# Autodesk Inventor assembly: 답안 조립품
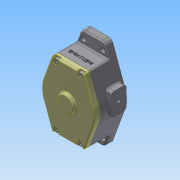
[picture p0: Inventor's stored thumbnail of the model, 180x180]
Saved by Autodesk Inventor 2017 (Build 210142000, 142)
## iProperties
Part Number: 답안 조립품
Material: 일반
Document SubType Name: Assembly
Designer: MRC
Author: MRC
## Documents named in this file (14)
- C:\Users\MRC\Desktop\731106V1008\답안 조립품.iam
- C:\Users\MRC\Desktop\731106V1008\본체.ipt
- C:\Users\MRC\Desktop\731106V1008\축.ipt
- C:\Users\MRC\Desktop\731106V1008\오일 실 14 25 4.ipt
- C:\Users\MRC\Desktop\731106V1008\오일레스 부시.ipt
- C:\Users\MRC\Desktop\731106V1008\내접기어.ipt
- C:\Users\MRC\Desktop\731106V1008\O링 G90.ipt
- C:\Users\MRC\Desktop\731106V1008\DU 부시.ipt
- C:\Users\MRC\Desktop\731106V1008\크레센트.ipt
- C:\Users\MRC\Desktop\731106V1008\육각 소켓 머리 볼트 M4 x 30.ipt
- C:\Users\MRC\Desktop\731106V1008\스퍼기어.ipt
- C:\Users\MRC\Desktop\731106V1008\평행 키 5x5x22.ipt
- C:\Users\MRC\Desktop\731106V1008\육각 소켓 머리 볼트 M6 x 12.ipt
- C:\Users\MRC\Desktop\731106V1008\커버.ipt
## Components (2 placed, 2 different names)
1. O링 G90:1
2. DU 부시:1
